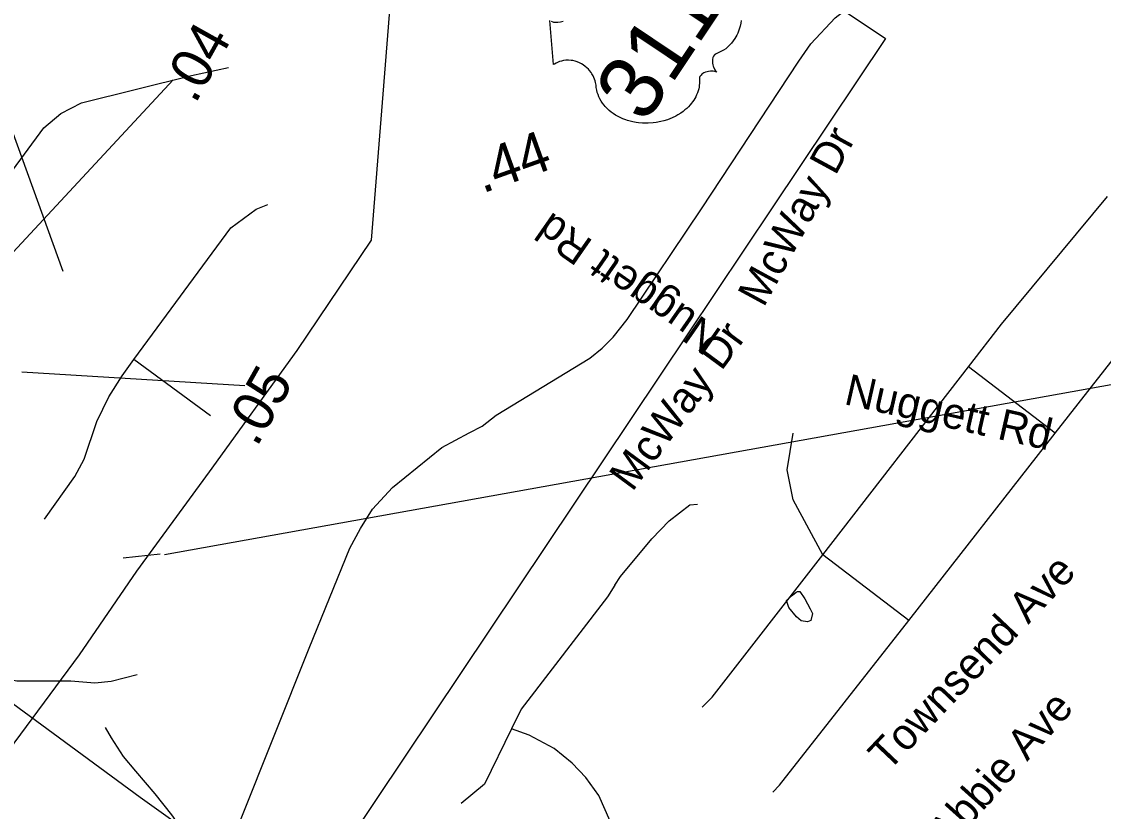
# Model space of a CAD drawing. Extents: x 1716282 to 1717158, y 799307 to 801078.
# Drawn here: x 1716928.81 to 1716976.74, y 800768.56 to 800803.55 of the extents above; entities that cross this region are included whole.
import ezdxf

# ---------------------------------------------------------------- set-up
doc = ezdxf.new("R2010")
doc.units = 0
for name, color, linetype in [('Exist Hydrographic Misc Water Feature', 7, 'Continuous'), ('Exist Road Non-System Type 51', 7, 'Continuous'), ('Exist Road Non-System Type 51 Label', 7, 'Continuous'), ('Exist Road Primary Interstate Mileage Hundredths English Label', 7, 'Continuous'), ('Exist Road Primary Interstate Structure Ovrhead Sign CELL', 7, 'Continuous'), ('Exist Road Primary US Mileage Hundredths English Label', 7, 'Continuous'), ('Exist Road Primary US Shield CELL', 7, 'Continuous'), ('Exist Road Primary US Shield Number Label', 7, 'Continuous'), ('Exist Road Primary US Structure Standard Bridge Number Label', 7, 'Continuous'), ('Exist Utilities Electrical Transmission Line', 7, 'Continuous'), ('Prop DSN Text', 7, 'Continuous')]:
    doc.layers.add(name, color=color, linetype=linetype)

msp = doc.modelspace()

# ---------------------------------------------------------------- linework, layer by layer
at = {"layer": 'Exist Hydrographic Misc Water Feature'}
for points in [[(1716963.184, 800778.305), (1716963.289, 800778.304), (1716963.518, 800777.972), (1716963.746, 800777.533), (1716963.848, 800777.323), (1716963.782, 800777.019), (1716963.626, 800776.948), (1716963.346, 800776.999), (1716963.147, 800777.17), (1716962.799, 800777.586), (1716962.696, 800777.9), (1716962.966, 800778.139), (1716963.128, 800778.273), (1716963.184, 800778.305)], [(1716963.184, 800778.305), (1716963.289, 800778.304), (1716963.518, 800777.972), (1716963.746, 800777.533), (1716963.848, 800777.323), (1716963.782, 800777.019), (1716963.626, 800776.948), (1716963.346, 800776.999), (1716963.147, 800777.17), (1716962.799, 800777.586), (1716962.696, 800777.9), (1716962.966, 800778.139), (1716963.128, 800778.273), (1716963.184, 800778.305)], [(1716933.929, 800774.612), (1716932.775, 800774.311), (1716932.057, 800774.239), (1716930.996, 800774.332), (1716928.599, 800774.319), (1716925.782, 800774.874), (1716923.974, 800775.263), (1716922.387, 800775.717), (1716920.581, 800776.106), (1716918.366, 800776.566), (1716917.379, 800776.819), (1716916.498, 800777.175), (1716916.01, 800777.437), (1716915.481, 800777.589), (1716914.62, 800777.613), (1716913.976, 800777.597), (1716913.125, 800777.687)], [(1716932.51, 800772.279), (1716932.786, 800771.808), (1716933.316, 800770.991), (1716933.855, 800770.34), (1716934.714, 800769.334), (1716935.451, 800768.408), (1716936.141, 800767.411), (1716936.677, 800766.551), (1716936.993, 800765.985), (1716937.339, 800765.256), (1716937.653, 800764.585), (1716938.366, 800763.571), (1716939.943, 800761.51), (1716940.316, 800761.08), (1716940.698, 800760.713), (1716941.083, 800760.452), (1716941.433, 800760.142), (1716941.726, 800759.696), (1716942.332, 800758.578)]]:
    msp.add_lwpolyline(points, dxfattribs=at)
at = {"layer": 'Exist Road Non-System Type 51'}
for p, q in [((1716974.609, 800785.309), (1716979.716, 800791.843)), ((1716937.186, 800786.082), (1716933.786, 800788.582)), ((1716964.307, 800779.919), (1716970.762, 800788.257)), ((1716974.609, 800785.309), (1716970.762, 800788.257)), ((1716968.128, 800777.013), (1716974.609, 800785.309)), ((1716968.128, 800777.013), (1716964.307, 800779.919))]:
    msp.add_line(p, q, dxfattribs=at)
for points in [[(1716948.638, 800785.327), (1716949.211, 800785.63), (1716949.835, 800786.111), (1716953.981, 800788.63), (1716954.533, 800789.085), (1716955.014, 800789.572), (1716955.648, 800790.354), (1716958.94, 800795.253), (1716963.242, 800801.796), (1716963.782, 800802.562), (1716964.861, 800803.714), (1716965.57, 800804.269), (1716966.514, 800804.893), (1716969.529, 800806.587), (1716973.505, 800808.938)], [(1716911.937, 800769.663), (1716915.216, 800776.131), (1716916.352, 800778.485), (1716917.197, 800781.005), (1716917.62, 800782.005), (1716918.147, 800782.952), (1716919.571, 800784.95), (1716929.79, 800798.849), (1716930.549, 800799.482), (1716931.467, 800799.943), (1716936.339, 800801.162), (1716937.976, 800801.508)], [(1716933.786, 800788.582), (1716938.078, 800794.406), (1716939.21, 800795.238), (1716939.714, 800795.45)], [(1716970.762, 800788.257), (1716972.223, 800790.145), (1716976.927, 800795.804)], [(1716929.829, 800781.508), (1716931.174, 800783.387), (1716931.58, 800784.166), (1716932.151, 800785.825), (1716932.682, 800786.926), (1716933.266, 800787.853), (1716933.786, 800788.582)], [(1716937.936, 800766.52), (1716938.483, 800768.095), (1716941.557, 800775.783), (1716943.352, 800780.215), (1716943.825, 800781.093), (1716944.362, 800781.949), (1716945.246, 800782.908), (1716947.434, 800784.678), (1716948.638, 800785.327)], [(1716964.307, 800779.919), (1716962.991, 800782.366), (1716962.733, 800783.692), (1716963.002, 800785.312)], [(1716955.091, 800778.576), (1716955.341, 800778.962), (1716956.728, 800780.631), (1716957.499, 800781.427), (1716958.42, 800782.145), (1716958.754, 800782.161)], [(1716958.97, 800773.177), (1716959.406, 800773.618), (1716964.307, 800779.919)], [(1716955.091, 800778.576), (1716954.763, 800778.063), (1716950.948, 800773.083), (1716950.523, 800772.209)], [(1716962.093, 800769.401), (1716962.393, 800769.719), (1716968.128, 800777.013)], [(1716927.122, 800774.275), (1716934.067, 800769.188), (1716937.584, 800766.669), (1716937.936, 800766.52)], [(1716950.523, 800772.209), (1716949.325, 800769.755), (1716948.288, 800768.911)], [(1716955.544, 800764.82), (1716955.494, 800765.671), (1716955.162, 800767.056), (1716954.883, 800768.124), (1716954.384, 800769.259), (1716953.817, 800770.054), (1716953.21, 800770.696), (1716952.4, 800771.339), (1716951.306, 800771.927), (1716950.523, 800772.209)]]:
    msp.add_lwpolyline(points, dxfattribs=at)
at = {"layer": 'Exist Road Primary Interstate Mileage Hundredths English Label'}
for p, q in [((1716927.865, 800792.71), (1716935.524, 800800.969)), ((1716928.821, 800788.024), (1716938.696, 800787.424))]:
    msp.add_line(p, q, dxfattribs=at)
at = {"layer": 'Exist Road Primary Interstate Structure Ovrhead Sign CELL'}
for p, q in [((1716935.139, 800779.935), (1716998.194, 800791.256)), ((1716933.309, 800779.797), (1716934.951, 800779.967))]:
    msp.add_line(p, q, dxfattribs=at)
at = {"layer": 'Exist Road Primary US Shield CELL'}
for points in [[(1716960.698, 800803.599), (1716960.677, 800803.486), (1716960.644, 800803.344), (1716960.57, 800803.12), (1716960.538, 800803.042), (1716960.496, 800802.952), (1716960.452, 800802.87), (1716960.407, 800802.793), (1716960.34, 800802.693), (1716960.266, 800802.599), (1716960.19, 800802.515), (1716960.104, 800802.431), (1716960.006, 800802.349), (1716959.907, 800802.281), (1716959.798, 800802.218), (1716959.592, 800802.126), (1716959.538, 800802.097), (1716959.514, 800802.075), (1716959.47, 800802.016), (1716959.443, 800801.951), (1716959.427, 800801.876), (1716959.422, 800801.828), (1716959.422, 800801.76), (1716959.426, 800801.704), (1716959.438, 800801.632), (1716959.453, 800801.579), (1716959.465, 800801.538), (1716959.505, 800801.446), (1716959.528, 800801.408), (1716959.56, 800801.362), (1716959.614, 800801.305), (1716959.52, 800801.338), (1716959.451, 800801.35), (1716959.388, 800801.354), (1716959.329, 800801.352), (1716959.247, 800801.342), (1716959.182, 800801.328), (1716959.11, 800801.306), (1716959.045, 800801.275), (1716958.996, 800801.248), (1716958.956, 800801.22), (1716958.914, 800801.181), (1716958.886, 800801.145), (1716958.866, 800801.114), (1716958.847, 800801.065), (1716958.85, 800800.979), (1716958.851, 800800.899), (1716958.848, 800800.814), (1716958.838, 800800.718), (1716958.828, 800800.649), (1716958.81, 800800.571), (1716958.786, 800800.482), (1716958.754, 800800.39), (1716958.715, 800800.298), (1716958.679, 800800.22), (1716958.635, 800800.139), (1716958.591, 800800.068), (1716958.542, 800799.997), (1716958.492, 800799.933), (1716958.433, 800799.86), (1716958.354, 800799.773), (1716958.282, 800799.705), (1716958.203, 800799.635), (1716958.117, 800799.566), (1716958.019, 800799.497), (1716957.891, 800799.415), (1716957.795, 800799.362), (1716957.636, 800799.283), (1716957.432, 800799.203), (1716957.265, 800799.151), (1716957.134, 800799.118), (1716956.929, 800799.079), (1716956.8, 800799.062), (1716956.579, 800799.047), (1716956.426, 800799.046), (1716956.318, 800799.051), (1716956.148, 800799.066), (1716956.045, 800799.08), (1716955.899, 800799.108), (1716955.77, 800799.139), (1716955.65, 800799.173), (1716955.576, 800799.198), (1716955.45, 800799.248), (1716955.363, 800799.285), (1716955.246, 800799.342), (1716955.128, 800799.41), (1716955.023, 800799.477), (1716954.939, 800799.538), (1716954.845, 800799.615), (1716954.75, 800799.703), (1716954.672, 800799.785), (1716954.618, 800799.848), (1716954.556, 800799.929), (1716954.492, 800800.024), (1716954.435, 800800.123), (1716954.392, 800800.211), (1716954.35, 800800.312), (1716954.319, 800800.405), (1716954.292, 800800.518), (1716954.273, 800800.629), (1716954.264, 800800.726), (1716954.241, 800800.849), (1716954.223, 800800.917), (1716954.192, 800801.004), (1716954.16, 800801.079), (1716954.129, 800801.143), (1716954.081, 800801.232), (1716954.04, 800801.293), (1716953.974, 800801.38), (1716953.923, 800801.435), (1716953.855, 800801.502), (1716953.788, 800801.561), (1716953.699, 800801.626), (1716953.622, 800801.675), (1716953.527, 800801.724), (1716953.431, 800801.764), (1716953.344, 800801.794), (1716953.238, 800801.819), (1716953.156, 800801.831), (1716953.039, 800801.838), (1716952.925, 800801.836), (1716952.824, 800801.822), (1716952.729, 800801.803), (1716952.65, 800801.777), (1716952.578, 800801.75), (1716952.495, 800801.712), (1716952.422, 800801.67), (1716952.38, 800801.641), (1716952.217, 800803.604)], [(1716952.272, 800803.572), (1716952.344, 800803.543), (1716952.383, 800803.531), (1716952.465, 800803.519), (1716952.57, 800803.518), (1716952.688, 800803.538), (1716952.801, 800803.572)]]:
    msp.add_lwpolyline(points, dxfattribs=at)
at = {"layer": 'Exist Road Primary US Structure Standard Bridge Number Label'}
msp.add_line((1716930.657, 800792.469), (1716901.927, 800871.786), dxfattribs=at)
at = {"layer": 'Exist Utilities Electrical Transmission Line'}
msp.add_lwpolyline([(1716921.466, 800731.735), (1716921.533, 800734.836), (1716921.394, 800738.417), (1716920.743, 800749.154), (1716920.518, 800756.737), (1716920.814, 800761.048), (1716924.052, 800765.647), (1716926.91, 800769.483), (1716931.371, 800775.492), (1716933.924, 800779.194), (1716937.136, 800783.596), (1716941.024, 800788.983), (1716944.315, 800793.864), (1716944.8, 800799.971), (1716945.692, 800811.122)], dxfattribs=at)
at = {"layer": 'Prop DSN Text'}
msp.add_lwpolyline([(1716644.267, 800417.02), (1716922.463, 800832.664), (1716967.08, 800802.801), (1716688.884, 800387.158)], close=True, dxfattribs=at)

# ---------------------------------------------------------------- texts
at = {"layer": 'Exist Road Non-System Type 51 Label'}
for s, rotation, p in [('McWay Dr', 61.4676, (1716961.69, 800790.846)), ('Nuggett Rd', 145.1448, (1716959.9, 800789.823)), ('McWay Dr', 53.6052, (1716955.867, 800782.68)), ('Nuggett Rd', 347.2386, (1716965.203, 800786.608)), ('Townsend Ave', 46.5108, (1716967.209, 800770.281)), ('Abbie Ave', 48.0698, (1716969.873, 800766.86))]:
    msp.add_text(s, height=1.3775, rotation=rotation, dxfattribs=at).set_placement(p)
at = {"layer": 'Exist Road Primary Interstate Mileage Hundredths English Label'}
for s, rotation, p in [('.04', 60.786, (1716936.503, 800799.862)), ('.05', 60.6032, (1716939.227, 800784.654))]:
    msp.add_text(s, height=1.8125, rotation=rotation, dxfattribs=at).set_placement(p)
at = {"layer": 'Exist Road Primary US Mileage Hundredths English Label'}
msp.add_text('.44', height=1.8125, rotation=19.6888, dxfattribs=at).set_placement((1716949.226, 800795.926))
at = {"layer": 'Exist Road Primary US Shield Number Label'}
msp.add_text('311', height=2.8275, rotation=56.2051, dxfattribs=at).set_placement((1716956.425, 800798.975))

doc.saveas('drawing.dxf')
